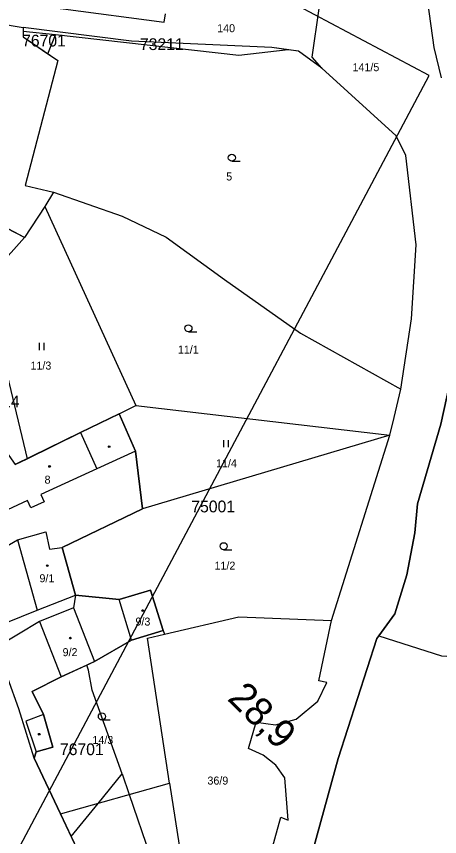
# Model space of a CAD drawing. Extents: x -794765 to -785424, y -1118958 to -1108731.
# Drawn here: x -789347.7 to -789257.8, y -1114452.9 to -1114278.7 of the extents above; entities that cross this region are included whole.
import ezdxf

# ---------------------------------------------------------------- set-up
doc = ezdxf.new("R2010")
doc.units = 0
for name, color, linetype in [('Level 66', 7, 'Continuous'), ('Level 71', 7, 'Continuous'), ('Level 73', 7, 'Continuous'), ('Level 75', 7, 'Continuous'), ('Level 76', 7, 'Continuous'), ('Level 77', 7, 'Continuous'), ('Level 79', 7, 'Continuous'), ('Level 81', 7, 'Continuous')]:
    doc.layers.add(name, color=color, linetype=linetype)

msp = doc.modelspace()

# ---------------------------------------------------------------- linework, layer by layer
at = {"layer": 'Level 66'}
for p, q in [((-789301.92, -1114309.43), (-789300.17, -1114309.43)), ((-789311.13, -1114345.66), (-789309.38, -1114345.66)), ((-789342.77, -1114349.54), (-789342.77, -1114348.04)), ((-789341.77, -1114349.54), (-789341.77, -1114348.04)), ((-789303.64, -1114370.19), (-789303.64, -1114368.69)), ((-789302.64, -1114370.19), (-789302.64, -1114368.69)), ((-789303.66, -1114391.97), (-789301.91, -1114391.97)), ((-789329.52, -1114428.12), (-789327.77, -1114428.12))]:
    msp.add_line(p, q, dxfattribs=at)
for centre in [(-789301.92, -1114308.68), (-789311.13, -1114344.91), (-789303.66, -1114391.22), (-789329.52, -1114427.37)]:
    msp.add_circle(centre, 0.75, dxfattribs=at)
at = {"layer": 'Level 71'}
msp.add_line((-789259.98, -1114291.21), (-790231.6, -1113775.02), dxfattribs=at)
msp.add_lwpolyline([(-790360.41, -1114017.5), (-789388.79, -1114533.68), (-789259.98, -1114291.21)], dxfattribs=at)
at = {"layer": 'Level 75'}
for p, q in [((-789355.8, -1114279.44), (-789346.22, -1114281.01)), ((-789345.93, -1114325.6), (-789379.32, -1114308.36)), ((-789339.77, -1114315.98), (-789341.65, -1114319.02)), ((-789341.65, -1114319.02), (-789345.93, -1114325.6)), ((-789341.65, -1114319.02), (-789322.32, -1114361.35)), ((-789353.07, -1114333.57), (-789345.93, -1114325.6)), ((-789325.87, -1114363.09), (-789322.32, -1114361.35)), ((-789322.32, -1114361.35), (-789268.36, -1114367.64)), ((-789268.36, -1114367.64), (-789320.91, -1114383.29)), ((-789280.75, -1114406.99), (-789268.36, -1114367.64)), ((-789337.93, -1114391.48), (-789320.91, -1114383.29)), ((-789335.13, -1114401.59), (-789337.93, -1114391.48)), ((-789325.85, -1114402.54), (-789335.13, -1114401.59)), ((-789323.24, -1114411.14), (-789325.85, -1114402.54)), ((-789283.43, -1114419.82), (-789280.75, -1114406.99)), ((-789323.24, -1114411.14), (-789316.49, -1114409.12)), ((-789316.49, -1114409.12), (-789316.24, -1114409.93)), ((-789338.28, -1114448.1), (-789343.91, -1114436.21)), ((-789338.28, -1114448.1), (-789315.13, -1114441.52)), ((-789315.13, -1114441.52), (-789308.78, -1114482.88))]:
    msp.add_line(p, q, dxfattribs=at)
for points in [[(-789257.37, -1114291.7), (-789258.94, -1114285.27), (-789260.26, -1114275.53)], [(-789339.08, -1114276.91), (-789337.76, -1114277.08), (-789316.27, -1114279.89), (-789316.04, -1114278.11)], [(-789282.8, -1114289.64), (-789284.89, -1114287.35), (-789283.39, -1114277.01)], [(-789346.22, -1114281.01), (-789346.23, -1114283.03), (-789338.89, -1114288.02), (-789345.79, -1114314.56), (-789339.77, -1114315.98)], [(-789282.8, -1114289.64), (-789287.78, -1114286.06), (-789293.45, -1114285.29), (-789323.26, -1114283.92), (-789346.22, -1114281.01)], [(-789266, -1114357.83), (-789263.75, -1114342.9), (-789262.78, -1114327.19), (-789264.96, -1114308.2), (-789267.05, -1114304.06), (-789282.8, -1114289.64)], [(-789270.71, -1114410.22), (-789267.29, -1114405.56), (-789264.73, -1114397.27), (-789263.02, -1114388.38), (-789262.46, -1114382.19), (-789257.56, -1114365.29), (-789253.33, -1114346.25), (-789251.18, -1114334.33), (-789250.9, -1114322.67), (-789252.39, -1114314.22)], [(-789339.77, -1114315.98), (-789325.21, -1114321.07), (-789315.86, -1114325.54), (-789303.51, -1114334.55), (-789287.32, -1114345.93), (-789266, -1114357.83)], [(-789268.36, -1114367.64), (-789267.46, -1114363.9), (-789266, -1114357.83)], [(-789325.87, -1114363.09), (-789334.03, -1114367.08), (-789347.91, -1114373.86)], [(-789320.91, -1114383.29), (-789322.35, -1114371.01), (-789325.87, -1114363.09)], [(-789356.78, -1114395.78), (-789355.02, -1114394.26), (-789347.44, -1114389.86), (-789341.4, -1114388.19), (-789340.64, -1114391.87), (-789337.93, -1114391.48)], [(-789316.49, -1114409.12), (-789319.19, -1114400.52), (-789325.85, -1114402.54)], [(-789352.96, -1114408.67), (-789343.28, -1114404.79), (-789335.13, -1114401.59)], [(-789316.24, -1114409.93), (-789300.41, -1114406.23), (-789280.75, -1114406.99)], [(-789343.91, -1114436.21), (-789347.12, -1114425.76), (-789351.91, -1114412.73), (-789352.96, -1114408.67)], [(-789315.13, -1114441.52), (-789319.85, -1114410.78), (-789316.24, -1114409.93)], [(-789343.91, -1114436.21), (-789343.44, -1114434.92), (-789339.96, -1114433.9), (-789341.95, -1114426.96), (-789344.29, -1114422.08), (-789338.16, -1114418.96), (-789331.1, -1114415.69), (-789323.24, -1114411.14)], [(-789295.13, -1114484.99), (-789294.08, -1114483.87), (-789292.39, -1114481.46), (-789290.93, -1114478.35), (-789289.8, -1114474.35), (-789285.34, -1114458.22), (-789279.32, -1114436.33), (-789271.12, -1114410.79), (-789270.71, -1114410.22)], [(-789270.71, -1114410.22), (-789257.37, -1114414.51), (-789223.48, -1114416.59)], [(-789307.22, -1114479.43), (-789303.82, -1114478.46), (-789300.96, -1114476.84), (-789298.42, -1114473.84), (-789291.48, -1114448.78), (-789289.96, -1114449.38), (-789290.68, -1114440.44), (-789292.59, -1114437.73), (-789295.23, -1114435.63), (-789298.36, -1114434.17), (-789296.75, -1114428.57), (-789292.67, -1114429.19), (-789288.24, -1114427.96), (-789283.63, -1114424.14), (-789281.74, -1114420.18), (-789283.43, -1114419.82)], [(-789308.78, -1114482.88), (-789313.67, -1114481.68), (-789318.19, -1114479.4), (-789321.47, -1114476.97), (-789326.78, -1114470.92), (-789329.07, -1114467.56), (-789338.28, -1114448.1)]]:
    msp.add_lwpolyline(points, dxfattribs=at)
at = {"layer": 'Level 77'}
for p, q in [((-789334.03, -1114367.08), (-789330.56, -1114374.77)), ((-789322.35, -1114371.01), (-789330.56, -1114374.77)), ((-789330.56, -1114374.77), (-789342.48, -1114380.22)), ((-789342.48, -1114380.22), (-789341.78, -1114381.76)), ((-789345.31, -1114381.51), (-789350.63, -1114383.96)), ((-789344.6, -1114383.06), (-789345.31, -1114381.51)), ((-789341.78, -1114381.76), (-789344.6, -1114383.06)), ((-789347.44, -1114389.86), (-789343.28, -1114404.79)), ((-789335.13, -1114401.59), (-789335.51, -1114404.28)), ((-789335.51, -1114404.28), (-789342.79, -1114407.21)), ((-789335.51, -1114404.28), (-789331.1, -1114415.69)), ((-789342.79, -1114407.21), (-789351.91, -1114412.73)), ((-789342.79, -1114407.21), (-789338.16, -1114418.96)), ((-789341.95, -1114426.96), (-789345.64, -1114428.37)), ((-789345.64, -1114428.37), (-789343.44, -1114434.92))]:
    msp.add_line(p, q, dxfattribs=at)
at = {"layer": 'Level 79'}
for centre in [(-789327.97, -1114370.07), (-789340.63, -1114374.27), (-789341.11, -1114395.33), (-789320.85, -1114404.88), (-789336.2, -1114410.74), (-789342.82, -1114431.15)]:
    msp.add_circle(centre, 0.175, dxfattribs=at)
at = {"layer": 'Level 81'}
for p, q in [((-789339.36, -1114282.58), (-789346.22, -1114281.9)), ((-789341, -1114286.58), (-789339.36, -1114282.58)), ((-789349.66, -1114354.88), (-789345.42, -1114372.64)), ((-789330.32, -1114445.84), (-789325.23, -1114439.56)), ((-789325.23, -1114439.56), (-789323.72, -1114443.96)), ((-789323.72, -1114443.96), (-789310.56, -1114482.44)), ((-789336.02, -1114452.87), (-789330.32, -1114445.84))]:
    msp.add_line(p, q, dxfattribs=at)
for points in [[(-789289.97, -1114285.76), (-789293.45, -1114285.29), (-789323.26, -1114283.92), (-789346.22, -1114281.01), (-789346.22, -1114281.9)], [(-789346.22, -1114281.9), (-789346.23, -1114283.03), (-789341, -1114286.58)], [(-789289.97, -1114285.76), (-789300.4, -1114286.94), (-789339.36, -1114282.58)], [(-789298.42, -1114473.84), (-789291.48, -1114448.78), (-789289.96, -1114449.38), (-789290.68, -1114440.44), (-789292.59, -1114437.73), (-789295.23, -1114435.63), (-789298.36, -1114434.17), (-789296.75, -1114428.57), (-789292.67, -1114429.19), (-789288.24, -1114427.96), (-789283.63, -1114424.14), (-789281.74, -1114420.18), (-789283.43, -1114419.82), (-789280.75, -1114406.99), (-789268.36, -1114367.64), (-789267.46, -1114363.9), (-789266, -1114357.83), (-789263.75, -1114342.9), (-789262.78, -1114327.19), (-789264.96, -1114308.2), (-789267.05, -1114304.06), (-789282.8, -1114289.64), (-789287.78, -1114286.06), (-789289.97, -1114285.76)], [(-789341, -1114286.58), (-789338.89, -1114288.02), (-789345.79, -1114314.56), (-789339.77, -1114315.98), (-789341.65, -1114319.02), (-789345.93, -1114325.6), (-789349.77, -1114323.62)], [(-789210.57, -1114341.6), (-789223.34, -1114334.35), (-789252.39, -1114314.22), (-789250.9, -1114322.67), (-789251.18, -1114334.33), (-789253.33, -1114346.25), (-789257.56, -1114365.29), (-789262.46, -1114382.19), (-789263.02, -1114388.38), (-789264.73, -1114397.27), (-789267.29, -1114405.56), (-789270.71, -1114410.22), (-789271.12, -1114410.79), (-789279.32, -1114436.33), (-789285.34, -1114458.22), (-789289.8, -1114474.35), (-789290.93, -1114478.35), (-789292.39, -1114481.46), (-789294.08, -1114483.87), (-789295.13, -1114484.99), (-789295.82, -1114485.71), (-789297.1, -1114486.75)], [(-789359.64, -1114350.23), (-789358.22, -1114359.34), (-789347.91, -1114373.86), (-789345.42, -1114372.64)], [(-789345.42, -1114372.64), (-789334.03, -1114367.08), (-789325.87, -1114363.09), (-789322.35, -1114371.01), (-789320.91, -1114383.29), (-789337.93, -1114391.48), (-789335.13, -1114401.59), (-789325.85, -1114402.54), (-789319.19, -1114400.52), (-789316.49, -1114409.12), (-789323.24, -1114411.14), (-789331.1, -1114415.69), (-789332.73, -1114416.45)], [(-789332.73, -1114416.45), (-789338.16, -1114418.96), (-789344.29, -1114422.08), (-789341.95, -1114426.96), (-789339.96, -1114433.9), (-789343.44, -1114434.92), (-789343.91, -1114436.21), (-789338.28, -1114448.1), (-789336.02, -1114452.87)], [(-789325.23, -1114439.56), (-789331.55, -1114421.78), (-789332.39, -1114417.54), (-789332.73, -1114416.45)], [(-789336.02, -1114452.87), (-789329.07, -1114467.56), (-789326.78, -1114470.92), (-789321.47, -1114476.97), (-789318.19, -1114479.4), (-789313.67, -1114481.68), (-789310.56, -1114482.44)]]:
    msp.add_lwpolyline(points, dxfattribs=at)

# ---------------------------------------------------------------- texts
at = {"layer": 'Level 73'}
msp.add_text('28,9', height=6, rotation=315.597, dxfattribs=at).set_placement((-789303.07, -1114423.77))
at = {"layer": 'Level 76'}
for s, p in [('140', (-789305.03, -1114282.02)), ('141/5', (-789276.29, -1114290.3)), ('5', (-789303.11, -1114313.52)), ('11/1', (-789313.38, -1114350.29)), ('11/3', (-789344.68, -1114353.69)), ('11/4', (-789305.27, -1114374.44)), ('8', (-789341.69, -1114377.92)), ('11/2', (-789305.6, -1114396.2)), ('9/1', (-789342.77, -1114398.87)), ('9/3', (-789322.38, -1114408.07)), ('9/2', (-789337.86, -1114414.57)), ('14/3', (-789331.53, -1114433.22)), ('36/9', (-789307.1, -1114441.85))]:
    msp.add_text(s, height=1.7, dxfattribs=at).set_placement(p)
at = {"layer": 'Level 81'}
for s, p in [('76701', (-789346.46, -1114285.05)), ('73211', (-789321.44, -1114285.81)), ('73214', (-789356.29, -1114361.7)), ('75001', (-789310.53, -1114384.02)), ('76701', (-789338.43, -1114435.6))]:
    msp.add_text(s, height=2.5, dxfattribs=at).set_placement(p)

doc.saveas('drawing.dxf')
